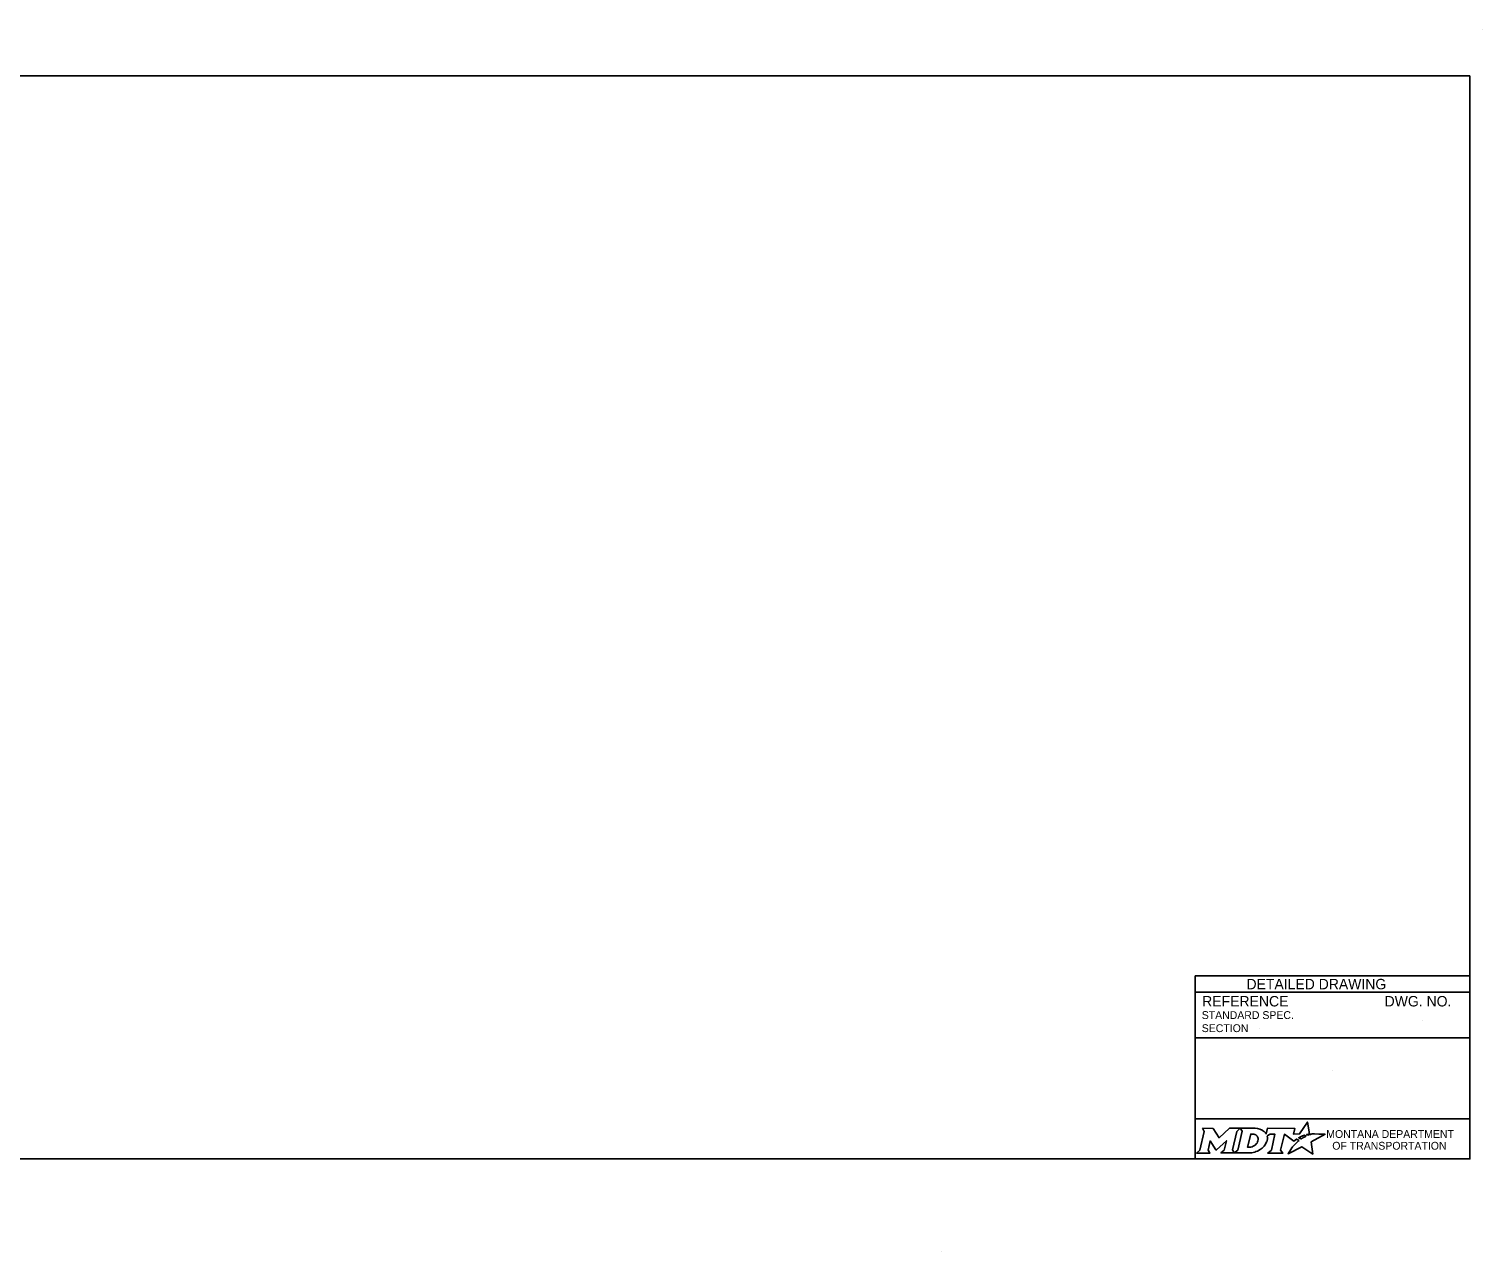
# Model space of a CAD drawing. Extents: x 49991.4 to 50021, y 49987.6 to 50011.4.
# Drawn here: x 50009.92 to 50021.04, y 49999.18 to 50008.52 of the extents above; entities that cross this region are included whole.
import ezdxf

# ---------------------------------------------------------------- set-up
doc = ezdxf.new("R2010")
doc.units = 0
for name, color, linetype in [('Default', 7, 'Continuous'), ('Level 1', 7, 'Continuous'), ('Level 4', 7, 'Continuous')]:
    doc.layers.add(name, color=color, linetype=linetype)

msp = doc.modelspace()

# ---------------------------------------------------------------- linework, layer by layer
at = {"layer": 'Default'}
for points in [[(50018.893, 50000.121), (50018.907, 50000.097), (50018.874, 49999.954), (50018.848, 49999.931), (50018.95, 49999.931), (50018.936, 49999.954), (50018.952, 50000.024), (50018.996, 49999.955), (50019.002, 49999.955), (50019.077, 50000.025), (50019.06, 49999.954), (50019.035, 49999.932), (50019.137, 49999.932), (50019.123, 49999.955), (50019.156, 50000.097)], [(50019.156, 50000.097), (50019.182, 50000.121), (50019.099, 50000.121), (50019.02, 50000.048), (50018.975, 50000.12), (50018.893, 50000.121)], [(50019.295, 50000.121), (50019.182, 50000.121), (50019.196, 50000.098), (50019.163, 49999.954), (50019.137, 49999.932), (50019.248, 49999.932)], [(50019.7, 50000.068), (50019.69, 50000.074), (50019.702, 50000.076), (50019.713, 50000.078), (50019.696, 50000.168), (50019.636, 50000.077), (50019.589, 50000.076), (50019.599, 50000.12), (50019.39, 50000.121), (50019.38, 50000.078), (50019.374, 50000.086)], [(50019.319, 50000.034), (50019.318, 50000.026), (50019.315, 50000.017), (50019.311, 50000.008), (50019.305, 50000.001), (50019.299, 49999.994), (50019.291, 49999.988), (50019.282, 49999.983), (50019.273, 49999.979), (50019.264, 49999.977), (50019.255, 49999.976), (50019.239, 49999.976), (50019.263, 50000.076), (50019.279, 50000.076), (50019.286, 50000.075), (50019.294, 50000.073), (50019.301, 50000.07), (50019.307, 50000.066), (50019.311, 50000.061), (50019.315, 50000.055), (50019.318, 50000.049), (50019.319, 50000.042), (50019.32, 50000.038), (50019.319, 50000.034)], [(50019.387, 50000.062), (50019.411, 50000.075), (50019.448, 50000.075), (50019.42, 49999.954), (50019.392, 49999.931), (50019.508, 49999.931), (50019.491, 49999.954), (50019.52, 50000.075), (50019.591, 50000.023), (50019.612, 50000.038), (50019.632, 50000.027)], [(50019.576, 49999.971), (50019.561, 49999.947), (50019.556, 49999.939), (50019.55, 49999.931), (50019.548, 49999.926), (50019.653, 49999.979), (50019.737, 49999.924), (50019.724, 50000.017), (50019.831, 50000.075), (50019.782, 50000.076), (50019.751, 50000.077), (50019.731, 50000.077), (50019.724, 50000.075), (50019.719, 50000.074), (50019.711, 50000.072), (50019.7, 50000.068)], [(50019.59, 49999.987), (50019.59, 49999.987)], [(50019.65, 50000.04), (50019.648, 50000.039), (50019.629, 50000.048), (50019.639, 50000.054), (50019.644, 50000.056), (50019.652, 50000.06), (50019.658, 50000.063), (50019.666, 50000.066), (50019.673, 50000.068), (50019.685, 50000.061), (50019.681, 50000.059), (50019.676, 50000.056), (50019.672, 50000.054), (50019.667, 50000.051), (50019.665, 50000.05), (50019.662, 50000.049), (50019.66, 50000.047), (50019.658, 50000.046), (50019.655, 50000.044), (50019.652, 50000.042), (50019.65, 50000.04)], [(50019.293, 49999.939), (50019.302, 49999.942), (50019.315, 49999.947), (50019.335, 49999.958)]]:
    msp.add_lwpolyline(points, dxfattribs=at)
for centre, radius, start, end in [((50019.274, 50000.059), 0.118, 300.9103, 339.1383), ((50019.319, 50000.042), 0.0709, 339.5329, 15.8582)]:
    msp.add_arc(centre, radius, start, end, dxfattribs=at)
for centre, major_axis, ratio, start_param, end_param in [((50019.293, 50000.073), (0.0834, -0.0037), 0.568097, 0.61298, 1.570796), ((50019.349, 50000.081), (0.0361, -0.0295), 0.469099, 1.225588, 1.570796), ((50019.583, 49999.979), (-0.00694, -0.00806), 0.008222, 0, 3.137361), ((50019.6, 49999.997), (-0.0098, -0.0102), 0.016458, 3.141593, 6.279097), ((50019.621, 50000.017), (-0.0112, -0.0097), 0.021651, 3.157348, 6.283185), ((50019.248, 50000.08), (0, 0.148), 0.987302, 3.139398, 3.456847)]:
    msp.add_ellipse(centre, major_axis=major_axis, ratio=ratio, start_param=start_param, end_param=end_param, dxfattribs=at)
at = {"layer": 'Level 1'}
for p, q in [((50021.038, 50008.524), (50021.038, 50008.524)), ((50016.9, 49999.176), (50016.9, 49999.176))]:
    msp.add_line(p, q, dxfattribs=at)
msp.add_lwpolyline([(50020.938, 50008.165), (50009.737, 50008.165), (50009.737, 49999.886), (50020.938, 49999.886)], close=True, dxfattribs=at)
at = {"layer": 'Level 4'}
for p, q in [((50020.938, 50001.286), (50018.838, 50001.286)), ((50018.838, 50001.286), (50018.838, 49999.886)), ((50020.938, 50001.161), (50018.838, 50001.161)), ((50019.332, 50000.886), (50019.332, 50000.886)), ((50020.574, 50000.946), (50020.574, 50000.946)), ((50020.938, 50000.811), (50018.838, 50000.811)), ((50019.888, 50000.562), (50019.888, 50000.562)), ((50020.938, 50000.193), (50018.838, 50000.193))]:
    msp.add_line(p, q, dxfattribs=at)

# ---------------------------------------------------------------- texts
at = {"layer": 'Default'}
for s, p in [('MONTANA DEPARTMENT', (50019.84, 50000.047)), ('OF TRANSPORTATION', (50019.886, 49999.957))]:
    msp.add_text(s, height=0.06, rotation=360, dxfattribs=at).set_placement(p)
at = {"layer": 'Level 4'}
for s, height, p in [('DETAILED DRAWING', 0.0799, (50019.23, 50001.183)), ('REFERENCE', 0.08, (50018.891, 50001.052)), ('DWG. NO.', 0.08, (50020.286, 50001.052)), ('STANDARD SPEC.', 0.06, (50018.888, 50000.956)), ('SECTION', 0.06, (50018.888, 50000.856))]:
    msp.add_text(s, height=height, dxfattribs=at).set_placement(p)

doc.saveas('drawing.dxf')
